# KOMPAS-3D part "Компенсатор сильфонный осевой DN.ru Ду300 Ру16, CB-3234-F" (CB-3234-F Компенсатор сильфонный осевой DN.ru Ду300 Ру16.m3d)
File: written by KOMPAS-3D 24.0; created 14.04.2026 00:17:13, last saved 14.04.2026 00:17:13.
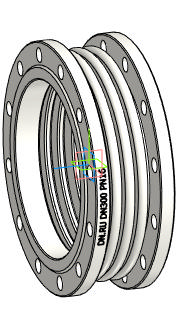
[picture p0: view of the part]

Document properties: Автор: DN.RU; Полное имя файла: D:\PROJECT CAD\DN.RU\...198(ACTUALE). CB-3234-F Компенсатор сильфонный осевой DN.ru\Исходники\DN300\CB-3234-F Компенсатор сильфонный осевой DN.ru Ду300 Ру16.m3d

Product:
- Body: Твердое тело1  | qty 1
    Масса: 44.600409
- Part/product: Компенсатор сильфонный осевой DN.ru Ду300 Ру16  | designation CB-3234-F
    Масса: 40
    Раздел спецификации: Прочие изделия
    Комментарий: D140-02121
    Примечание: D140-02121
    additional columns: Типовые

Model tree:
1. Твердое тело1  (labels: Твердое тело1)

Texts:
  CB-3234-F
